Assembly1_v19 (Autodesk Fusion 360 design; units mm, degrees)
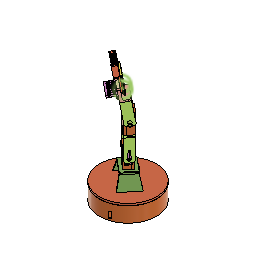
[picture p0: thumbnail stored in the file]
component_insert "Component Insert5"
joint "Assemble" alignAngle 180 alignOffsetX 0 alignOffsetY 0 alignOffsetZ 0
component_insert "Component Insert6"
component_insert "Component Insert7"
joint "Assemble" alignAngle 180 alignOffsetX 0 alignOffsetY 0 alignOffsetZ 0
component_insert "Component Insert11"
component_insert "Component Insert13"
component_insert "Component Insert16"
component_insert "Component Insert17"
joint "Assemble" alignAngle 22 alignOffsetX 0 alignOffsetY 0 alignOffsetZ 0
joint "Assemble" alignAngle 0 alignOffsetX 0 alignOffsetY 0 alignOffsetZ 0
joint "Assemble" alignAngle 0 alignOffsetX 0 alignOffsetY 0 alignOffsetZ 0
component_insert "Component Insert19"
joint "Assemble" alignAngle 180 alignOffsetX 0 alignOffsetY 0 alignOffsetZ 0
component_insert "Component Insert20"
joint "Assemble" alignAngle 0 alignOffsetX 0 alignOffsetY 0 alignOffsetZ 0
joint "Assemble" alignAngle -180 alignOffsetX 0 alignOffsetY 0 alignOffsetZ 0
joint "Assemble" alignAngle -180 alignOffsetX 0 alignOffsetY 0 alignOffsetZ 0
joint "Assemble" alignAngle 180 alignOffsetX 0 alignOffsetY 0 alignOffsetZ 0
component_insert "Component Insert21"
joint "Assemble" alignAngle 0 alignOffsetX 0 alignOffsetY 0 alignOffsetZ 0
component_insert "Component Insert23"
joint "Assemble" alignAngle 180 alignOffsetX 0 alignOffsetY 0 alignOffsetZ 0
component_insert "Component Insert24"
joint "Assemble" alignAngle 180 alignOffsetX 0 alignOffsetY 0 alignOffsetZ 0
